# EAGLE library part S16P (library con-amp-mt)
AMP MT CONNECTOR
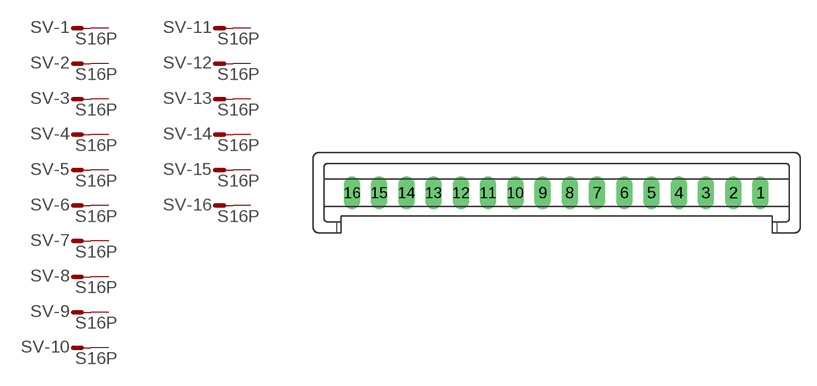
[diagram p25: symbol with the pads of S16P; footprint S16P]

Designator prefix SV; gates -1=M -2=M -3=M -4=M -5=M -6=M -7=M -8=M -9=M -10=M -11=M -12=M -13=M -14=M -15=M -16=M

## S16P (OC_FARNELL: unknown; OC_NEWARK: unknown)  [S16P]
1  -1:S  pas
2  -2:S  pas
3  -3:S  pas
4  -4:S  pas
5  -5:S  pas
6  -6:S  pas
7  -7:S  pas
8  -8:S  pas
9  -9:S  pas
10  -10:S  pas
11  -11:S  pas
12  -12:S  pas
13  -13:S  pas
14  -14:S  pas
15  -15:S  pas
16  -16:S  pas

## Footprint S16P (pad centres in mm)
AMP MT CONNECTOR
drill 1.016 long: 1 18.75,0; 2 16.25,0; 3 13.75,0; 4 11.25,0; 5 8.75,0; 6 6.25,0; 7 3.75,0; 8 1.25,0; 9 -1.25,0; 10 -3.75,0; 11 -6.25,0; 12 -8.75,0; 13 -11.25,0; 14 -13.75,0; 15 -16.25,0; 16 -18.74,0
